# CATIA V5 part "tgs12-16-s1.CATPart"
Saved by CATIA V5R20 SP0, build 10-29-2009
Part number: TGS12-16-S1
Revision: 1
Definition: design
Nomenclature: TGS12-16-S1
Source: made
Description: NOT SPECIFIED
Bounding box of the stored display mesh (mm): x -22 to 0.8, y 0 to 12, z -5 to 5
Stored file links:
  C:\Users\Raffaele\Desktop\3D X SITO CF\I-MOLD\TGS-S1\tgs12-s1.step\tgs12-16-s1.CATPart
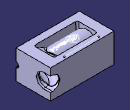
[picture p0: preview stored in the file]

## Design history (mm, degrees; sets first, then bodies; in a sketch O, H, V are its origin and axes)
Set1
  Line1 "LINE #3964": stored without definition
  DatumCurve1 "COMPOSITE_CURVE #4019"
  DatumCurve2 "COMPOSITE_CURVE #4068"
  DatumCurve3 "COMPOSITE_CURVE #4147"
  DatumCurve4 "COMPOSITE_CURVE #4190"
  DatumCurve5 "COMPOSITE_CURVE #4419"
  DatumCurve6 "COMPOSITE_CURVE #4560"
  DatumCurve7 "COMPOSITE_CURVE #4587"
  DatumCurve8 "COMPOSITE_CURVE #4645"
  DatumCurve9 "COMPOSITE_CURVE #4702"
  DatumCurve10 "COMPOSITE_CURVE #4731"
  DatumSurface1 "OPEN_SHELL #3954"
Body1 "MANIFOLD_SOLID_BREP #3955" (main body)
  Solid1: solid without history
